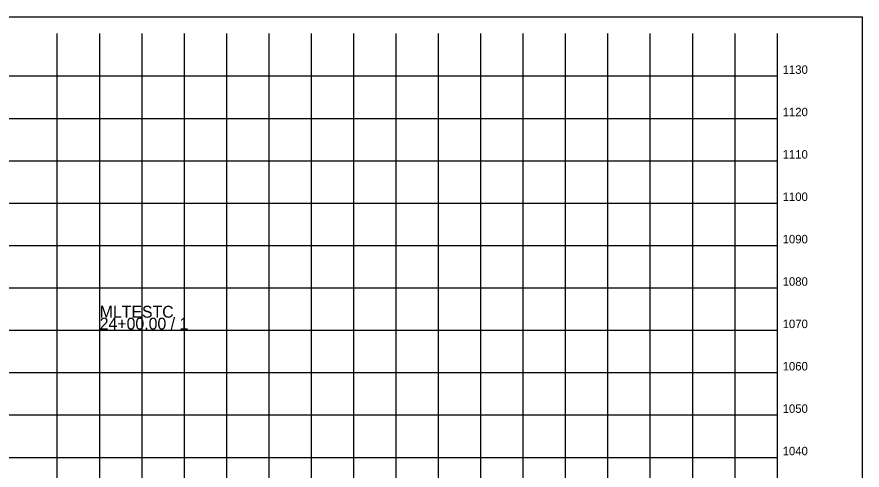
# Model space of a CAD drawing. Extents: x 1131015 to 1136271, y 133453 to 174329.
# Drawn here: x 1132310.9 to 1132510.5, y 155219.7 to 155326.6 of the extents above; entities that cross this region are included whole.
import ezdxf

# ---------------------------------------------------------------- set-up
doc = ezdxf.new("R2010")
doc.units = 0
for name, color, linetype in [('DESIGN - SHEET - Corner Text', 7, 'Continuous'), ('DESIGN - SHEET - Light Grid', 7, 'Continuous'), ('DESIGN - SHEET - Linework', 7, 'Continuous'), ('DESIGN - SHEET - Plot Shape', 7, 'Continuous')]:
    doc.layers.add(name, color=color, linetype=linetype)

msp = doc.modelspace()

# ---------------------------------------------------------------- linework, layer by layer
at = {"layer": 'DESIGN - SHEET - Light Grid'}
msp.add_line((1132340.46, 155167.66), (1132340.46, 155255.62), dxfattribs=at)
at = {"layer": 'DESIGN - SHEET - Linework'}
for p, q in [((1132320.46, 155112.66), (1132320.46, 155322.66)), ((1132330.46, 155112.66), (1132330.46, 155322.66)), ((1132340.46, 155112.66), (1132340.46, 155322.66)), ((1132350.46, 155112.66), (1132350.46, 155322.66)), ((1132360.46, 155112.66), (1132360.46, 155322.66)), ((1132370.46, 155112.66), (1132370.46, 155322.66)), ((1132380.46, 155112.66), (1132380.46, 155322.66)), ((1132390.46, 155112.66), (1132390.46, 155322.66)), ((1132400.46, 155112.66), (1132400.46, 155322.66)), ((1132410.46, 155112.66), (1132410.46, 155322.66)), ((1132420.46, 155112.66), (1132420.46, 155322.66)), ((1132430.46, 155112.66), (1132430.46, 155322.66)), ((1132440.46, 155112.66), (1132440.46, 155322.66)), ((1132450.46, 155112.66), (1132450.46, 155322.66)), ((1132460.46, 155112.66), (1132460.46, 155322.66)), ((1132470.46, 155112.66), (1132470.46, 155322.66)), ((1132480.46, 155112.66), (1132480.46, 155322.66)), ((1132190.46, 155312.66), (1132490.46, 155312.66)), ((1132190.46, 155302.66), (1132490.46, 155302.66)), ((1132190.46, 155292.66), (1132490.46, 155292.66)), ((1132190.46, 155282.66), (1132490.46, 155282.66)), ((1132190.46, 155272.66), (1132490.46, 155272.66)), ((1132190.46, 155262.66), (1132490.46, 155262.66)), ((1132190.46, 155252.66), (1132490.46, 155252.66)), ((1132190.46, 155242.66), (1132490.46, 155242.66)), ((1132190.46, 155232.66), (1132490.46, 155232.66)), ((1132190.46, 155222.66), (1132490.46, 155222.66))]:
    msp.add_line(p, q, dxfattribs=at)
msp.add_lwpolyline([(1132190.46, 155322.66), (1132190.46, 155112.66), (1132490.46, 155112.66), (1132490.46, 155322.66)], dxfattribs=at)
at = {"layer": 'DESIGN - SHEET - Plot Shape'}
msp.add_lwpolyline([(1132170.46, 155326.6), (1132510.46, 155326.6), (1132510.46, 155108.72), (1132170.46, 155108.72)], close=True, dxfattribs=at)

# ---------------------------------------------------------------- texts
at = {"layer": 'DESIGN - SHEET - Corner Text'}
for s, p in [('1130', (1132491.7, 155313.16)), ('1120', (1132491.7, 155303.16)), ('1110', (1132491.7, 155293.16)), ('1100', (1132491.7, 155283.16)), ('1090', (1132491.7, 155273.16)), ('1080', (1132491.7, 155263.16)), ('1070', (1132491.7, 155253.16)), ('1060', (1132491.7, 155243.16)), ('1050', (1132491.7, 155233.16)), ('1040', (1132491.7, 155223.16))]:
    msp.add_text(s, height=2, dxfattribs=at).set_placement(p)
at = {"layer": 'DESIGN - SHEET - Light Grid'}
for s, p in [('MLTESTC', (1132330.46, 155255.62)), ('24+00.00 / 1', (1132330.46, 155252.82))]:
    msp.add_text(s, height=2.8, dxfattribs=at).set_placement(p)

doc.saveas('drawing.dxf')
